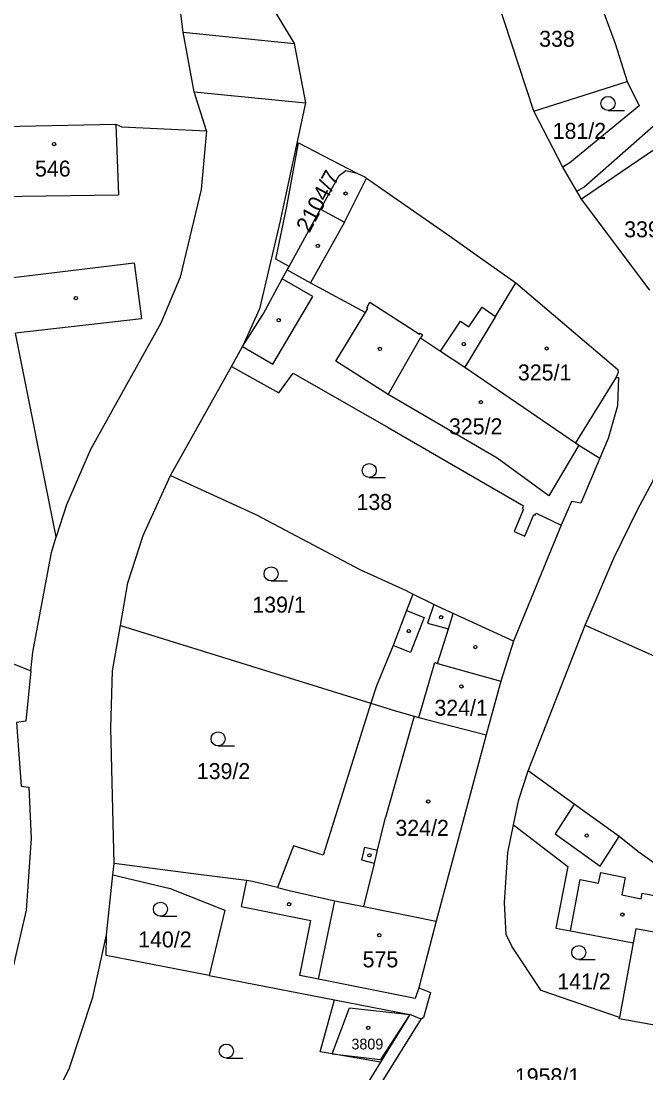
# Model space of a CAD drawing. Extents: x -679220 to -673243, y -1075091 to -1066557.
# Drawn here: x -676729.1 to -676662.6, y -1071294.6 to -1071182.6 of the extents above; entities that cross this region are included whole.
import ezdxf

# ---------------------------------------------------------------- set-up
doc = ezdxf.new("R2010")
doc.units = 0
for name, color, linetype in [('Hranice parcel', 7, 'Continuous'), ('Parcelní čísla', 7, 'Continuous'), ('Vnitřní kresba', 7, 'Continuous'), ('Značky budov', 7, 'Continuous'), ('Značky kultur', 7, 'Continuous')]:
    doc.layers.add(name, color=color, linetype=linetype)

msp = doc.modelspace()

# ---------------------------------------------------------------- linework, layer by layer
at = {"layer": 'Hranice parcel'}
for p, q in [((-676674.54, -1071192.22), (-676679.33, -1071177.62)), ((-676671.44, -1071198.18), (-676674.54, -1071192.22)), ((-676661.56, -1071196.25), (-676669.46, -1071201.6)), ((-676669.96, -1071200.75), (-676671.44, -1071198.18)), ((-676669.46, -1071201.6), (-676669.96, -1071200.75)), ((-676662.19, -1071211.28), (-676669.46, -1071201.6)), ((-676700.78, -1071209.12), (-676700.57, -1071208.74)), ((-676725.35, -1071237.51), (-676729.68, -1071215.85)), ((-676713.2, -1071230.99), (-676706.71, -1071219.41)), ((-676671.61, -1071236.29), (-676676.7, -1071248.61)), ((-676718.53, -1071246.94), (-676691.86, -1071255.22)), ((-676675.13, -1071262.42), (-676669.07, -1071246.91)), ((-676679.61, -1071258.57), (-676684.93, -1071278.41)), ((-676719.32, -1071273.46), (-676719.19, -1071272.28)), ((-676720.01, -1071279.87), (-676719.32, -1071273.46)), ((-676709.07, -1071284.2), (-676695.74, -1071286.79)), ((-676695.74, -1071286.79), (-676687.74, -1071288.35)), ((-676687.74, -1071288.35), (-676690.84, -1071293.39))]:
    msp.add_line(p, q, dxfattribs=at)
for points in [[(-676714.26, -1071159.56), (-676706.99, -1071170.4), (-676704.8, -1071174.72), (-676703.28, -1071179.64), (-676700.03, -1071185.04), (-676698.82, -1071191.33), (-676701.52, -1071203.91), (-676703.72, -1071213.25), (-676705.55, -1071217.25)], [(-676709.37, -1071194.33), (-676710.67, -1071190.16), (-676711.86, -1071183.83), (-676712.45, -1071179.03), (-676715.29, -1071173.8), (-676725.22, -1071168.28)], [(-676669.96, -1071200.75), (-676669.2, -1071200.31), (-676661.84, -1071193.82), (-676649.68, -1071187.97), (-676647.3, -1071184.53), (-676650.76, -1071183.01), (-676653.23, -1071177.35), (-676660.03, -1071176.21), (-676661.37, -1071172.06)], [(-676674.54, -1071192.22), (-676664.58, -1071189.06), (-676663.3, -1071191.67), (-676670.69, -1071197.74), (-676671.44, -1071198.18)], [(-676732.7, -1071193.9), (-676719.03, -1071193.62), (-676718.39, -1071193.91), (-676709.37, -1071194.33)], [(-676709.37, -1071194.33), (-676709.92, -1071200.57), (-676712.17, -1071209.89), (-676714.22, -1071214.77), (-676721.73, -1071228.24), (-676724.28, -1071234.11), (-676725.35, -1071237.51)], [(-676700.57, -1071208.74), (-676702, -1071207.96), (-676700.83, -1071202.36), (-676699.56, -1071195.59), (-676693.35, -1071198.84)], [(-676700.57, -1071208.74), (-676697.22, -1071202.64), (-676695.26, -1071199.06), (-676694.54, -1071198.56), (-676693.35, -1071198.84)], [(-676693.35, -1071198.84), (-676692.52, -1071199.23), (-676692.32, -1071199.37), (-676689.08, -1071201.64), (-676683.51, -1071205.49), (-676680.54, -1071207.58), (-676676.43, -1071210.5), (-676665.6, -1071219.7), (-676665.54, -1071220.05), (-676665.77, -1071220.52), (-676665.5, -1071220.58), (-676665.63, -1071223.59), (-676666.6, -1071227.04), (-676667.5, -1071229.16)], [(-676705.55, -1071217.25), (-676703.33, -1071213.83), (-676701.3, -1071210.06), (-676700.78, -1071209.12)], [(-676700.78, -1071209.12), (-676698.28, -1071210.5), (-676692.45, -1071213.65), (-676692.2, -1071213.23), (-676692.31, -1071213.16), (-676691.98, -1071212.55), (-676686.69, -1071215.94), (-676686.63, -1071215.84), (-676686.36, -1071216.01), (-676686.59, -1071216.36), (-676684.45, -1071217.77), (-676681.87, -1071219.46), (-676670.09, -1071227.5), (-676669.73, -1071227.78), (-676667.5, -1071229.16)], [(-676706.71, -1071219.41), (-676705.96, -1071218.06), (-676705.55, -1071217.25)], [(-676706.71, -1071219.41), (-676701.68, -1071222.2), (-676700.13, -1071220.09), (-676690.04, -1071225.87), (-676675.61, -1071234.21), (-676675.77, -1071234.51), (-676675.63, -1071234.57), (-676676.62, -1071236.96), (-676675.47, -1071237.46), (-676674.52, -1071235.15), (-676674.4, -1071235.2), (-676674.29, -1071235.01), (-676671.61, -1071236.29)], [(-676669.07, -1071246.91), (-676666.01, -1071239.77), (-676663.47, -1071234.59), (-676661.89, -1071231.66), (-676660.89, -1071229.31), (-676660.05, -1071227.58), (-676659.49, -1071226.94), (-676658.89, -1071226.62), (-676658.14, -1071226.49), (-676656.61, -1071226.19), (-676654.4, -1071226.19), (-676651.4, -1071226.48), (-676646.63, -1071228.01), (-676634.79, -1071231.61), (-676628.22, -1071233.43), (-676623.19, -1071234.33)], [(-676667.5, -1071229.16), (-676669.53, -1071233.92), (-676670.53, -1071233.75), (-676671.61, -1071236.29)], [(-676718.53, -1071246.94), (-676717.75, -1071242.41), (-676716.11, -1071237.36), (-676713.2, -1071230.99)], [(-676713.2, -1071230.99), (-676704.1, -1071235.14), (-676693.06, -1071240.99), (-676688.12, -1071243.24), (-676687.39, -1071243.61)], [(-676728.05, -1071251.79), (-676727.84, -1071249.8), (-676725.87, -1071239.18), (-676725.35, -1071237.51)], [(-676687.39, -1071243.61), (-676688.07, -1071245.37), (-676689.5, -1071249.09), (-676691.28, -1071253.37), (-676691.86, -1071255.22)], [(-676676.7, -1071248.61), (-676683.1, -1071245.68), (-676684.74, -1071244.94), (-676685.17, -1071244.72), (-676687.39, -1071243.61)], [(-676753.77, -1071270.45), (-676746.06, -1071244.57), (-676728.05, -1071251.79)], [(-676719.19, -1071272.28), (-676719.54, -1071257.88), (-676719.37, -1071251.76), (-676718.53, -1071246.94)], [(-676669.07, -1071246.91), (-676655.09, -1071253.14), (-676651.15, -1071254.81)], [(-676676.7, -1071248.61), (-676678.04, -1071252.87), (-676679.61, -1071258.57)], [(-676728.05, -1071251.79), (-676728.6, -1071257.13), (-676729.58, -1071257.28), (-676729.09, -1071264.03), (-676728.27, -1071264.14), (-676728.02, -1071269.56), (-676728.56, -1071277.24), (-676730.07, -1071283.83), (-676730.72, -1071285.73)], [(-676691.86, -1071255.22), (-676696.96, -1071271.37), (-676700.1, -1071270.38), (-676701.82, -1071274.81)], [(-676691.86, -1071255.22), (-676689.14, -1071256.06), (-676687.27, -1071256.58), (-676686.78, -1071256.73), (-676679.61, -1071258.57)], [(-676676.68, -1071268.15), (-676676.13, -1071265.47), (-676675.13, -1071262.42)], [(-676654.03, -1071277.54), (-676656.36, -1071276.08), (-676663.44, -1071270.99), (-676665.46, -1071269.41), (-676670.24, -1071265.95), (-676675.13, -1071262.42)], [(-676665.4, -1071288.65), (-676673.74, -1071285.78), (-676676.84, -1071281.12), (-676677.48, -1071279.84), (-676677.65, -1071276.41), (-676677.28, -1071271.09), (-676676.68, -1071268.15)], [(-676676.68, -1071268.15), (-676670.9, -1071272.59), (-676672.2, -1071279.14), (-676670.63, -1071279.44), (-676663.95, -1071280.71), (-676665.4, -1071288.65)], [(-676701.82, -1071274.81), (-676704.46, -1071274.17), (-676705.1, -1071274.09), (-676710.23, -1071273.44), (-676719.19, -1071272.28)], [(-676719.32, -1071273.46), (-676713.22, -1071274.93), (-676707.42, -1071277.25), (-676709.07, -1071284.2)], [(-676701.82, -1071274.81), (-676700.57, -1071275.13), (-676695.71, -1071276.26), (-676692.61, -1071276.86), (-676684.93, -1071278.41)], [(-676684.93, -1071278.41), (-676686.77, -1071285.5), (-676685.53, -1071285.98), (-676686.26, -1071288.65), (-676686.5, -1071288.84), (-676687.74, -1071288.35)], [(-676727.54, -1071301.18), (-676723.99, -1071294.13), (-676721.47, -1071286.48), (-676720.01, -1071279.87)], [(-676709.07, -1071284.2), (-676720.06, -1071282.06), (-676720.01, -1071279.87)], [(-676690.84, -1071293.39), (-676695.98, -1071292.52), (-676697.26, -1071292.3), (-676695.74, -1071286.79)], [(-676652.19, -1071290.84), (-676653.74, -1071290.88), (-676665.43, -1071288.8), (-676665.4, -1071288.65)], [(-676690.84, -1071293.39), (-676692.33, -1071295.83), (-676692.72, -1071296.73), (-676695.19, -1071300.9), (-676699.2, -1071306.32), (-676702.25, -1071310.72)]]:
    msp.add_lwpolyline(points, dxfattribs=at)
at = {"layer": 'Vnitřní kresba'}
for p, q in [((-676669.59, -1071174.88), (-676665.88, -1071185.03)), ((-676711.86, -1071183.83), (-676700.03, -1071185.04)), ((-676665.88, -1071185.03), (-676664.58, -1071189.06)), ((-676710.67, -1071190.16), (-676698.82, -1071191.33)), ((-676719.03, -1071193.62), (-676718.74, -1071201.13)), ((-676694.68, -1071204.04), (-676692.32, -1071199.37)), ((-676732.59, -1071201.31), (-676718.74, -1071201.13)), ((-676697.22, -1071202.64), (-676694.68, -1071204.04)), ((-676694.68, -1071204.04), (-676698.28, -1071210.5)), ((-676730.84, -1071210.04), (-676717.08, -1071208.37)), ((-676717.08, -1071208.37), (-676716.27, -1071214.31)), ((-676698.04, -1071211.95), (-676701.3, -1071210.06)), ((-676678.6, -1071214.07), (-676676.43, -1071210.5)), ((-676702.29, -1071219.15), (-676698.04, -1071211.95)), ((-676681.44, -1071215.17), (-676680.04, -1071213.1)), ((-676680.04, -1071213.1), (-676678.6, -1071214.07)), ((-676716.27, -1071214.31), (-676729.68, -1071215.85)), ((-676695.6, -1071218.84), (-676692.45, -1071213.65)), ((-676684.45, -1071217.77), (-676682.34, -1071214.56)), ((-676682.34, -1071214.56), (-676681.44, -1071215.17)), ((-676678.6, -1071214.07), (-676681.87, -1071219.46)), ((-676690.04, -1071222.36), (-676686.59, -1071216.36)), ((-676705.55, -1071217.25), (-676702.29, -1071219.15)), ((-676690.04, -1071222.36), (-676695.6, -1071218.84)), ((-676665.77, -1071220.52), (-676670.09, -1071227.5)), ((-676678.44, -1071229.14), (-676690.04, -1071222.36)), ((-676669.73, -1071227.78), (-676672.92, -1071233.14)), ((-676672.92, -1071233.14), (-676678.44, -1071229.14)), ((-676685.17, -1071244.72), (-676685.83, -1071246.71)), ((-676688.07, -1071245.37), (-676686.21, -1071246.09)), ((-676683.61, -1071247.29), (-676683.1, -1071245.68)), ((-676686.21, -1071246.09), (-676687.64, -1071249.81)), ((-676685.83, -1071246.71), (-676683.61, -1071247.29)), ((-676684.79, -1071250.99), (-676683.61, -1071247.29)), ((-676687.64, -1071249.81), (-676689.5, -1071249.09)), ((-676686.78, -1071256.73), (-676685.08, -1071250.88)), ((-676685.08, -1071250.88), (-676684.79, -1071250.99)), ((-676684.79, -1071250.99), (-676678.04, -1071252.87)), ((-676687.27, -1071256.58), (-676690.3, -1071267.36)), ((-676670.24, -1071265.95), (-676672.25, -1071269.11)), ((-676691.15, -1071270.85), (-676690.3, -1071267.36)), ((-676672.25, -1071269.11), (-676667.47, -1071272.57)), ((-676667.47, -1071272.57), (-676665.46, -1071269.41)), ((-676692.85, -1071271.93), (-676692.51, -1071270.52)), ((-676692.51, -1071270.52), (-676691.15, -1071270.85)), ((-676691.49, -1071272.26), (-676691.15, -1071270.85)), ((-676691.49, -1071272.26), (-676692.85, -1071271.93)), ((-676692.61, -1071276.86), (-676691.49, -1071272.26)), ((-676670.63, -1071279.44), (-676669.6, -1071273.99)), ((-676669.6, -1071273.99), (-676667.63, -1071274.37)), ((-676667.63, -1071274.37), (-676667.41, -1071273.24)), ((-676667.41, -1071273.24), (-676664.81, -1071273.75)), ((-676664.81, -1071273.75), (-676665.17, -1071275.62)), ((-676705.1, -1071274.09), (-676705.66, -1071276.83)), ((-676697.45, -1071284.59), (-676695.71, -1071276.26)), ((-676665.17, -1071275.62), (-676663.11, -1071276.02)), ((-676663.11, -1071276.02), (-676662.99, -1071275.43)), ((-676662.99, -1071275.43), (-676659.94, -1071276.02)), ((-676705.66, -1071276.83), (-676698.26, -1071278.34)), ((-676699.43, -1071284.19), (-676698.26, -1071278.34)), ((-676663.68, -1071279.22), (-676663.95, -1071280.71)), ((-676660.6, -1071279.79), (-676663.68, -1071279.22)), ((-676697.45, -1071284.59), (-676699.43, -1071284.19)), ((-676687.15, -1071286.65), (-676697.45, -1071284.59)), ((-676686.77, -1071285.5), (-676687.15, -1071286.65)), ((-676695.98, -1071292.52), (-676694.14, -1071287.62)), ((-676694.14, -1071287.62), (-676687.74, -1071288.35)), ((-676687.74, -1071288.35), (-676690.84, -1071293.12)), ((-676700.61, -1071311.38), (-676686.5, -1071288.84)), ((-676695.98, -1071292.52), (-676690.84, -1071293.12))]:
    msp.add_line(p, q, dxfattribs=at)
at = {"layer": 'Značky budov'}
for centre in [(-676725.59, -1071195.74), (-676694.56, -1071200.99), (-676697.53, -1071206.56), (-676723.26, -1071212.11), (-676701.67, -1071214.47), (-676681.99, -1071217.01), (-676690.91, -1071217.52), (-676673.16, -1071217.48), (-676680.16, -1071223.19), (-676684.4, -1071246.07), (-676687.83, -1071247.55), (-676680.75, -1071249.24), (-676682.23, -1071253.43), (-676685.76, -1071265.67), (-676668.9, -1071269.3), (-676692.03, -1071271.4), (-676700.58, -1071276.6), (-676665.1, -1071277.71), (-676690.98, -1071279.9), (-676692.15, -1071289.76)]:
    msp.add_circle(centre, 0.175, dxfattribs=at)
at = {"layer": 'Značky kultur'}
for p, q in [((-676666.63, -1071192.16), (-676664.88, -1071192.16)), ((-676692.05, -1071231.21), (-676690.3, -1071231.21)), ((-676702.49, -1071242.21), (-676700.74, -1071242.21)), ((-676708.13, -1071259.76), (-676706.38, -1071259.76)), ((-676714.27, -1071277.88), (-676712.52, -1071277.88)), ((-676669.74, -1071282.49), (-676667.99, -1071282.49)), ((-676707.25, -1071292.98), (-676705.5, -1071292.98))]:
    msp.add_line(p, q, dxfattribs=at)
for centre in [(-676666.63, -1071191.41), (-676692.05, -1071230.46), (-676702.49, -1071241.46), (-676708.13, -1071259.01), (-676714.27, -1071277.13), (-676669.74, -1071281.74), (-676707.25, -1071292.23)]:
    msp.add_circle(centre, 0.75, dxfattribs=at)

# ---------------------------------------------------------------- texts
at = {"layer": 'Parcelní čísla'}
for s, height, p in [('338', 1.7, (-676673.96, -1071185.38)), ('181/2', 1.7, (-676672.52, -1071195.18)), ('546', 1.7, (-676727.62, -1071199.19)), ('339/1', 1.7, (-676664.91, -1071205.65)), ('325/1', 1.7, (-676676.22, -1071220.88)), ('325/2', 1.7, (-676683.56, -1071226.61)), ('138', 1.7, (-676693.4, -1071234.66)), ('139/1', 1.7, (-676704.49, -1071245.58)), ('324/1', 1.7, (-676685.11, -1071256.55)), ('139/2', 1.7, (-676710.4, -1071263.29)), ('324/2', 1.7, (-676689.26, -1071269.33)), ('140/2', 1.7, (-676716.64, -1071281.2)), ('575', 1.7, (-676692.75, -1071283.32)), ('141/2', 1.7, (-676672.03, -1071285.67)), ('3809', 1.14, (-676693.94, -1071292.05)), ('1958/1', 1.7, (-676676.55, -1071295.75))]:
    msp.add_text(s, height=height, dxfattribs=at).set_placement(p)
msp.add_text('2104/7', height=1.7, rotation=62, dxfattribs=at).set_placement((-676698.42, -1071205.27))

doc.saveas('drawing.dxf')
